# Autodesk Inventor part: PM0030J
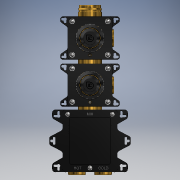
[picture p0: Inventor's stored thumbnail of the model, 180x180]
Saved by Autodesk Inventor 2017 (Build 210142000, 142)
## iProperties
Created: 2021-09
Part Number: PM0030J
Material: Generico
Document SubType Name: Modeling
Designer: CIANI
Density: 1 g/cm^3
Appearance: Default
Author: CIANI
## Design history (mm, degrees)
feature "Base2"
node "Solido1"
node "Solido3"
